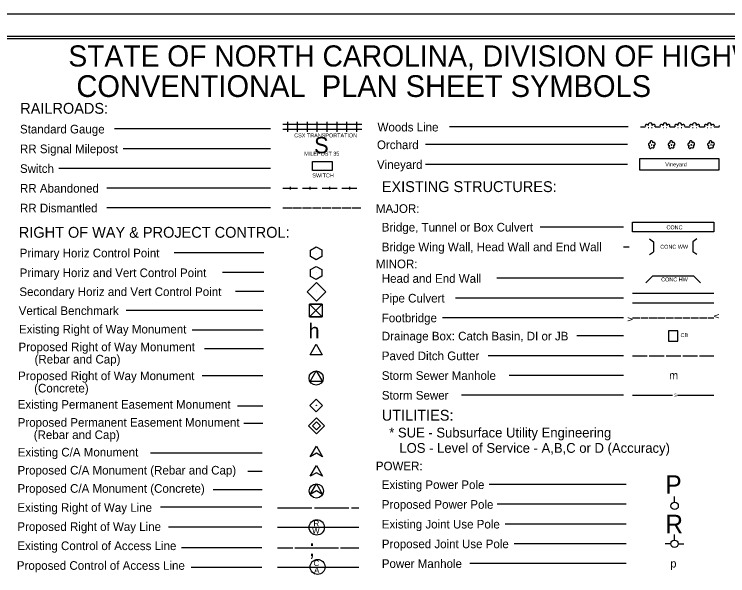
# Model space of a CAD drawing. Extents: x -167 to 1517, y -26 to 1074.
# Drawn here: x 396 to 1119, y 505 to 1074 of the extents above; entities that cross this region are included whole.
import ezdxf

# ---------------------------------------------------------------- set-up
doc = ezdxf.new("R2010")
doc.units = 0
for name, color, linetype in [('Default', 7, 'Continuous'), ('Sheet Cutting Line CELL', 7, 'Continuous'), ('Sheet Plot Border Inside CELL', 7, 'Continuous'), ('Sheet Plot Border Outside CELL', 7, 'Continuous'), ('Sheet Symbology CELL', 7, 'Continuous')]:
    doc.layers.add(name, color=color, linetype=linetype)

msp = doc.modelspace()

# ---------------------------------------------------------------- linework, layer by layer
at = {"layer": 'Default'}
for p, q in [((701.87, 831.68), (701.87, 831.68)), ((701.86, 811.71), (701.86, 811.71)), ((702, 792.64), (702, 792.64)), ((701.49, 773.64), (701.49, 773.64)), ((701.96, 677.42), (701.96, 677.42)), ((702.14, 656.81), (702.14, 656.81))]:
    msp.add_line(p, q, dxfattribs=at)
for points in [[(701.87, 825.03), (696.07, 828.32), (696.07, 834.97), (701.87, 838.33), (707.66, 835.04), (707.66, 828.32), (701.87, 825.03)], [(707.97, 780.11), (695, 767.14), (701.48, 773.63), (707.97, 767.14), (695, 780.11)], [(701.48, 773.63), (707.97, 780.11), (695, 780.11), (701.48, 773.63)], [(701.48, 773.63), (695, 767.14), (707.97, 767.14), (701.48, 773.63)]]:
    msp.add_lwpolyline(points, dxfattribs=at)
for points in [[(696.03, 815.09), (701.89, 818.36), (707.76, 815.13), (707.67, 808.41), (701.8, 805.01), (696.03, 808.28)], [(692.59, 792.67), (702.04, 802.13), (711.52, 792.65), (702.06, 783.2)], [(695, 780.11), (707.97, 780.11), (707.97, 767.14), (695, 767.14)], [(695.46, 677.42), (701.96, 683.91), (708.45, 677.42), (701.96, 670.92)], [(702.14, 664.86), (710.19, 656.81), (702.14, 648.76), (694.08, 656.81)], [(702.14, 660.84), (706.16, 656.81), (702.14, 652.79), (698.11, 656.81)]]:
    msp.add_lwpolyline(points, close=True, dxfattribs=at)
msp.add_circle((701.96, 677.42), 0.126, dxfattribs=at)
at = {"layer": 'Sheet Cutting Line CELL'}
msp.add_line((1517, 1073.98), (-167, 1073.98), dxfattribs=at)
at = {"layer": 'Sheet Plot Border Inside CELL'}
msp.add_lwpolyline([(-154, -3.57), (1512.5, -3.57), (1512.5, 1051.53), (-154, 1051.53)], close=True, dxfattribs=at)
at = {"layer": 'Sheet Plot Border Outside CELL'}
msp.add_lwpolyline([(-167, -26.02), (1517, -26.02), (1517, 1073.98), (-167, 1073.98)], close=True, dxfattribs=at)
at = {"layer": 'Sheet Symbology CELL'}
for p, q in [((668.02, 962.44), (678.02, 962.44)), ((673.02, 954.94), (673.02, 964.94)), ((678.02, 962.44), (688.02, 962.44)), ((683.02, 954.94), (683.02, 964.94)), ((688.02, 962.44), (698.02, 962.44)), ((693.02, 954.94), (693.02, 964.94)), ((698.02, 962.44), (708.02, 962.44)), ((703.02, 954.94), (703.02, 964.94)), ((708.02, 962.44), (718.02, 962.44)), ((713.02, 954.94), (713.02, 964.94)), ((718.02, 962.44), (728.02, 962.44)), ((723.02, 954.94), (723.02, 964.94)), ((728.02, 962.44), (738.02, 962.44)), ((733.02, 954.94), (733.02, 964.94)), ((738.02, 962.44), (748.02, 962.44)), ((743.02, 954.94), (743.02, 964.94)), ((655.63, 957.67), (497.22, 957.67)), ((668.02, 957.44), (678.02, 957.44)), ((678.02, 957.44), (688.02, 957.44)), ((688.02, 957.44), (698.02, 957.44)), ((698.02, 957.44), (708.02, 957.44)), ((708.02, 957.44), (718.02, 957.44)), ((718.02, 957.44), (728.02, 957.44)), ((728.02, 957.44), (738.02, 957.44)), ((738.02, 957.44), (748.02, 957.44)), ((1018.26, 959.72), (837.14, 959.72)), ((1030.65, 959.72), (1035.65, 959.72)), ((1038.6, 959.22), (1039.1, 959.22)), ((1042.1, 959.22), (1042.6, 959.22)), ((1045.65, 959.72), (1050.65, 959.72)), ((1053.6, 959.22), (1054.1, 959.22)), ((1057.1, 959.22), (1057.6, 959.22)), ((1060.65, 959.72), (1065.65, 959.72)), ((1068.6, 959.22), (1069.1, 959.22)), ((1072.1, 959.22), (1072.6, 959.22)), ((1075.65, 959.72), (1080.65, 959.72)), ((1083.6, 959.22), (1084.1, 959.22)), ((1087.1, 959.22), (1087.6, 959.22)), ((1090.65, 959.72), (1095.65, 959.72)), ((1098.6, 959.22), (1099.1, 959.22)), ((1102.1, 959.22), (1102.6, 959.22)), ((1105.65, 959.72), (1110.65, 959.72)), ((1017.7, 941.79), (812.76, 941.79)), ((655.63, 937.67), (506.08, 937.67)), ((1017.7, 921.79), (812.76, 921.79)), ((655.63, 917.67), (440.72, 917.67)), ((655.63, 897.67), (489.47, 897.67)), ((668.02, 897.67), (683.02, 897.67)), ((675.52, 898.92), (675.52, 896.42)), ((688.02, 897.67), (703.02, 897.67)), ((695.52, 898.92), (695.52, 896.42)), ((708.02, 897.67), (723.02, 897.67)), ((715.52, 898.92), (715.52, 896.42)), ((728.02, 897.67), (743.02, 897.67)), ((735.52, 898.92), (735.52, 896.42)), ((655.63, 877.67), (489.47, 877.67)), ((655.63, 877.67), (489.47, 877.67)), ((668.02, 877.67), (677.02, 877.67)), ((678.02, 877.67), (687.02, 877.67)), ((688.02, 877.67), (697.02, 877.67)), ((698.02, 877.67), (707.02, 877.67)), ((708.02, 877.67), (717.02, 877.67)), ((718.02, 877.67), (727.02, 877.67)), ((728.02, 877.67), (737.02, 877.67)), ((738.02, 877.67), (747.02, 877.67)), ((1013.38, 858.28), (928.96, 858.28)), ((1039.83, 846.15), (1043.93, 843.28)), ((1043.93, 843.28), (1043.93, 833.28)), ((1088.03, 846.15), (1083.93, 843.28)), ((1083.93, 843.28), (1083.93, 833.28)), ((1013.38, 838.28), (1019.37, 838.28)), ((1039.83, 830.42), (1043.93, 833.28)), ((1088.03, 830.42), (1083.93, 833.28)), ((648.94, 832.05), (557.9, 832.05)), ((648.94, 812.05), (607.02, 812.05)), ((1013.38, 806.29), (885.08, 806.29)), ((1036.23, 801.71), (1043.31, 808.79)), ((1043.31, 808.79), (1084.56, 808.79)), ((1084.56, 808.79), (1091.63, 801.71)), ((648.62, 792.85), (620.07, 792.85)), ((1022.68, 791.29), (1105.18, 791.29)), ((1013.38, 786.29), (843.19, 786.29)), ((1022.68, 781.29), (1105.18, 781.29)), ((647.93, 773.63), (509.09, 773.63)), ((1013.38, 766.29), (829.91, 766.29)), ((1022.68, 766.29), (1030.18, 766.29)), ((1031.18, 766.29), (1038.68, 766.29)), ((1039.68, 766.29), (1047.18, 766.29)), ((1048.18, 766.29), (1055.68, 766.29)), ((1056.68, 766.29), (1064.18, 766.29)), ((1065.18, 766.29), (1072.68, 766.29)), ((1073.68, 766.29), (1081.18, 766.29)), ((1082.18, 766.29), (1089.68, 766.29)), ((1090.68, 766.29), (1098.18, 766.29)), ((1099.18, 766.29), (1105.18, 766.29)), ((648.25, 753.64), (576.2, 753.64)), ((1013.38, 747.85), (966.18, 747.85)), ((648.35, 734.86), (588.61, 734.86)), ((701.86, 732.24), (701.86, 732.24)), ((1013.38, 727.85), (876.43, 727.85)), ((1022.68, 727.85), (1037.68, 727.85)), ((1039.68, 727.85), (1054.68, 727.85)), ((1056.68, 727.85), (1071.68, 727.85)), ((1073.68, 727.85), (1088.68, 727.85)), ((1090.68, 727.85), (1105.18, 727.85)), ((647.84, 707.46), (586.36, 707.46)), ((701.88, 705.18), (701.88, 705.18)), ((1013.38, 707.85), (897.71, 707.85)), ((1013.38, 687.85), (849.18, 687.85)), ((1022.68, 687.85), (1063.21, 687.85)), ((1068.21, 687.85), (1105.18, 687.85)), ((647.92, 676.76), (622.13, 676.76)), ((647.92, 659.14), (628.65, 659.14)), ((695.87, 625.24), (702.12, 636.04)), ((702.12, 636.04), (708.37, 625.24)), ((646.93, 628.92), (533.69, 628.92)), ((702.12, 628.84), (695.87, 625.24)), ((708.37, 625.24), (702.12, 628.84)), ((695.84, 605.62), (702.09, 616.42)), ((702.09, 616.42), (708.34, 605.62)), ((647.03, 610.39), (632.46, 610.39)), ((702.09, 609.22), (695.84, 605.62)), ((708.34, 605.62), (702.09, 609.22)), ((695.84, 587.12), (702.09, 597.92)), ((702.09, 597.92), (708.34, 587.12)), ((1016.17, 597.17), (877.47, 597.17)), ((647.03, 591.88), (597.36, 591.88)), ((702.09, 590.72), (695.84, 587.12)), ((708.34, 587.12), (702.09, 590.72)), ((1065.39, 579.28), (1065.39, 584.91)), ((646.59, 574.1), (544.07, 574.1)), ((662.62, 573.53), (697.62, 573.53)), ((700.12, 573.53), (735.12, 573.53)), ((737.62, 573.53), (745.12, 573.53)), ((1016.17, 577.17), (885.26, 577.17)), ((1016.17, 557.17), (893.66, 557.17)), ((646.59, 554.1), (552.06, 554.1)), ((662.62, 553.98), (745.12, 553.98)), ((1065.18, 540.93), (1065.18, 546.56)), ((1016.17, 537.17), (902.66, 537.17)), ((1061.43, 537.18), (1055.81, 537.18)), ((1068.93, 537.18), (1074.56, 537.18)), ((646.59, 532.98), (565.27, 532.98)), ((662.62, 532.98), (678.08, 532.98)), ((680.08, 532.98), (724.49, 532.98)), ((726.49, 532.98), (745.12, 532.98)), ((1016.17, 517.17), (857.67, 517.17)), ((646.59, 513.16), (574.94, 513.16)), ((662.62, 513.54), (745.12, 513.54))]:
    msp.add_line(p, q, dxfattribs=at)
for points in [[(1500, 1048.98), (0, 1048.98), (0, 0), (1500, 0)], [(698.02, 924.64), (718.02, 924.64), (718.02, 915.54), (698.02, 915.54)], [(1059.12, 742.54), (1068.73, 742.54), (1068.73, 753.18), (1059.12, 753.18)], [(695.61, 728.64), (701.86, 739.44), (708.11, 728.64)], [(695.63, 701.58), (701.88, 712.38), (708.13, 701.58)]]:
    msp.add_lwpolyline(points, close=True, dxfattribs=at)
for points in [[(1043.14, 943.54), (1043.29, 943.84), (1043.34, 944.14), (1043.29, 944.44), (1043.24, 944.74), (1043.09, 944.99), (1042.94, 945.24), (1042.69, 945.44), (1042.44, 945.59), (1042.09, 945.69), (1041.84, 945.69), (1041.54, 945.64), (1041.24, 945.54), (1040.99, 945.39), (1040.74, 945.19), (1040.59, 944.89), (1040.49, 944.64), (1040.44, 944.34), (1040.44, 944.04), (1040.49, 943.74), (1040.64, 943.49), (1040.84, 943.19), (1040.59, 943.34), (1040.29, 943.39), (1039.99, 943.39), (1039.74, 943.29), (1039.49, 943.19), (1039.24, 942.99), (1039.04, 942.79), (1038.89, 942.54), (1038.84, 942.29), (1038.79, 941.94), (1038.84, 941.69), (1038.94, 941.44), (1039.14, 941.19), (1039.29, 940.99), (1039.54, 940.84), (1039.84, 940.69), (1040.09, 940.64), (1040.39, 940.64), (1040.14, 940.54), (1039.89, 940.34), (1039.74, 940.14), (1039.64, 939.84), (1039.54, 939.54), (1039.54, 939.29), (1039.59, 938.99), (1039.74, 938.74), (1039.89, 938.49), (1040.09, 938.29), (1040.34, 938.14), (1040.59, 938.04), (1040.89, 938.04), (1041.19, 938.04), (1041.44, 938.09), (1041.69, 938.29), (1041.94, 938.44), (1042.19, 938.89)], [(1042.29, 941.79), (1042.14, 941.79), (1042.04, 941.74), (1041.94, 941.69), (1041.94, 941.54), (1041.94, 941.44), (1042.04, 941.34), (1042.19, 941.34), (1042.29, 941.34), (1042.39, 941.44), (1042.44, 941.59), (1042.39, 941.69), (1042.29, 941.79)], [(1042.19, 938.89), (1042.79, 938.54), (1043.09, 938.44), (1043.39, 938.39), (1043.69, 938.44), (1043.94, 938.54), (1044.19, 938.69), (1044.44, 938.89), (1044.59, 939.14), (1044.69, 939.39), (1044.79, 939.69), (1044.74, 939.99), (1044.69, 940.29), (1044.49, 940.59), (1044.34, 940.79), (1044.09, 940.94), (1043.79, 941.09), (1044.09, 941.04), (1044.44, 941.04), (1044.69, 941.14), (1044.99, 941.29), (1045.24, 941.44), (1045.44, 941.69), (1045.59, 941.99), (1045.64, 942.29), (1045.69, 942.59), (1045.64, 942.89), (1045.54, 943.19), (1045.34, 943.44), (1045.09, 943.69), (1044.84, 943.84), (1044.54, 943.94), (1044.24, 943.99), (1043.94, 943.99), (1043.64, 943.89), (1043.39, 943.74), (1043.14, 943.54)], [(1063.14, 943.54), (1063.29, 943.84), (1063.34, 944.14), (1063.29, 944.44), (1063.24, 944.74), (1063.09, 944.99), (1062.94, 945.24), (1062.69, 945.44), (1062.44, 945.59), (1062.09, 945.69), (1061.84, 945.69), (1061.54, 945.64), (1061.24, 945.54), (1060.99, 945.39), (1060.74, 945.19), (1060.59, 944.89), (1060.49, 944.64), (1060.44, 944.34), (1060.44, 944.04), (1060.49, 943.74), (1060.64, 943.49), (1060.84, 943.19), (1060.59, 943.34), (1060.29, 943.39), (1059.99, 943.39), (1059.74, 943.29), (1059.49, 943.19), (1059.24, 942.99), (1059.04, 942.79), (1058.89, 942.54), (1058.84, 942.29), (1058.79, 941.94), (1058.84, 941.69), (1058.94, 941.44), (1059.14, 941.19), (1059.29, 940.99), (1059.54, 940.84), (1059.84, 940.69), (1060.09, 940.64), (1060.39, 940.64), (1060.14, 940.54), (1059.89, 940.34), (1059.74, 940.14), (1059.64, 939.84), (1059.54, 939.54), (1059.54, 939.29), (1059.59, 938.99), (1059.74, 938.74), (1059.89, 938.49), (1060.09, 938.29), (1060.34, 938.14), (1060.59, 938.04), (1060.89, 938.04), (1061.19, 938.04), (1061.44, 938.09), (1061.69, 938.29), (1061.94, 938.44), (1062.19, 938.89)], [(1062.29, 941.79), (1062.14, 941.79), (1062.04, 941.74), (1061.94, 941.69), (1061.94, 941.54), (1061.94, 941.44), (1062.04, 941.34), (1062.19, 941.34), (1062.29, 941.34), (1062.39, 941.44), (1062.44, 941.59), (1062.39, 941.69), (1062.29, 941.79)], [(1062.19, 938.89), (1062.79, 938.54), (1063.09, 938.44), (1063.39, 938.39), (1063.69, 938.44), (1063.94, 938.54), (1064.19, 938.69), (1064.44, 938.89), (1064.59, 939.14), (1064.69, 939.39), (1064.79, 939.69), (1064.74, 939.99), (1064.69, 940.29), (1064.49, 940.59), (1064.34, 940.79), (1064.09, 940.94), (1063.79, 941.09), (1064.09, 941.04), (1064.44, 941.04), (1064.69, 941.14), (1064.99, 941.29), (1065.24, 941.44), (1065.44, 941.69), (1065.59, 941.99), (1065.64, 942.29), (1065.69, 942.59), (1065.64, 942.89), (1065.54, 943.19), (1065.34, 943.44), (1065.09, 943.69), (1064.84, 943.84), (1064.54, 943.94), (1064.24, 943.99), (1063.94, 943.99), (1063.64, 943.89), (1063.39, 943.74), (1063.14, 943.54)], [(1083.14, 943.54), (1083.29, 943.84), (1083.34, 944.14), (1083.29, 944.44), (1083.24, 944.74), (1083.09, 944.99), (1082.94, 945.24), (1082.69, 945.44), (1082.44, 945.59), (1082.09, 945.69), (1081.84, 945.69), (1081.54, 945.64), (1081.24, 945.54), (1080.99, 945.39), (1080.74, 945.19), (1080.59, 944.89), (1080.49, 944.64), (1080.44, 944.34), (1080.44, 944.04), (1080.49, 943.74), (1080.64, 943.49), (1080.84, 943.19), (1080.59, 943.34), (1080.29, 943.39), (1079.99, 943.39), (1079.74, 943.29), (1079.49, 943.19), (1079.24, 942.99), (1079.04, 942.79), (1078.89, 942.54), (1078.84, 942.29), (1078.79, 941.94), (1078.84, 941.69), (1078.94, 941.44), (1079.14, 941.19), (1079.29, 940.99), (1079.54, 940.84), (1079.84, 940.69), (1080.09, 940.64), (1080.39, 940.64), (1080.14, 940.54), (1079.89, 940.34), (1079.74, 940.14), (1079.64, 939.84), (1079.54, 939.54), (1079.54, 939.29), (1079.59, 938.99), (1079.74, 938.74), (1079.89, 938.49), (1080.09, 938.29), (1080.34, 938.14), (1080.59, 938.04), (1080.89, 938.04), (1081.19, 938.04), (1081.44, 938.09), (1081.69, 938.29), (1081.94, 938.44), (1082.19, 938.89)], [(1082.29, 941.79), (1082.14, 941.79), (1082.04, 941.74), (1081.94, 941.69), (1081.94, 941.54), (1081.94, 941.44), (1082.04, 941.34), (1082.19, 941.34), (1082.29, 941.34), (1082.39, 941.44), (1082.44, 941.59), (1082.39, 941.69), (1082.29, 941.79)], [(1082.19, 938.89), (1082.79, 938.54), (1083.09, 938.44), (1083.39, 938.39), (1083.69, 938.44), (1083.94, 938.54), (1084.19, 938.69), (1084.44, 938.89), (1084.59, 939.14), (1084.69, 939.39), (1084.79, 939.69), (1084.74, 939.99), (1084.69, 940.29), (1084.49, 940.59), (1084.34, 940.79), (1084.09, 940.94), (1083.79, 941.09), (1084.09, 941.04), (1084.44, 941.04), (1084.69, 941.14), (1084.99, 941.29), (1085.24, 941.44), (1085.44, 941.69), (1085.59, 941.99), (1085.64, 942.29), (1085.69, 942.59), (1085.64, 942.89), (1085.54, 943.19), (1085.34, 943.44), (1085.09, 943.69), (1084.84, 943.84), (1084.54, 943.94), (1084.24, 943.99), (1083.94, 943.99), (1083.64, 943.89), (1083.39, 943.74), (1083.14, 943.54)], [(1103.14, 943.54), (1103.29, 943.84), (1103.34, 944.14), (1103.29, 944.44), (1103.24, 944.74), (1103.09, 944.99), (1102.94, 945.24), (1102.69, 945.44), (1102.44, 945.59), (1102.09, 945.69), (1101.84, 945.69), (1101.54, 945.64), (1101.24, 945.54), (1100.99, 945.39), (1100.74, 945.19), (1100.59, 944.89), (1100.49, 944.64), (1100.44, 944.34), (1100.44, 944.04), (1100.49, 943.74), (1100.64, 943.49), (1100.84, 943.19), (1100.59, 943.34), (1100.29, 943.39), (1099.99, 943.39), (1099.74, 943.29), (1099.49, 943.19), (1099.24, 942.99), (1099.04, 942.79), (1098.89, 942.54), (1098.84, 942.29), (1098.79, 941.94), (1098.84, 941.69), (1098.94, 941.44), (1099.14, 941.19), (1099.29, 940.99), (1099.54, 940.84), (1099.84, 940.69), (1100.09, 940.64), (1100.39, 940.64), (1100.14, 940.54), (1099.89, 940.34), (1099.74, 940.14), (1099.64, 939.84), (1099.54, 939.54), (1099.54, 939.29), (1099.59, 938.99), (1099.74, 938.74), (1099.89, 938.49), (1100.09, 938.29), (1100.34, 938.14), (1100.59, 938.04), (1100.89, 938.04), (1101.19, 938.04), (1101.44, 938.09), (1101.69, 938.29), (1101.94, 938.44), (1102.19, 938.89)], [(1102.29, 941.79), (1102.14, 941.79), (1102.04, 941.74), (1101.94, 941.69), (1101.94, 941.54), (1101.94, 941.44), (1102.04, 941.34), (1102.19, 941.34), (1102.29, 941.34), (1102.39, 941.44), (1102.44, 941.59), (1102.39, 941.69), (1102.29, 941.79)], [(1102.19, 938.89), (1102.79, 938.54), (1103.09, 938.44), (1103.39, 938.39), (1103.69, 938.44), (1103.94, 938.54), (1104.19, 938.69), (1104.44, 938.89), (1104.59, 939.14), (1104.69, 939.39), (1104.79, 939.69), (1104.74, 939.99), (1104.69, 940.29), (1104.49, 940.59), (1104.34, 940.79), (1104.09, 940.94), (1103.79, 941.09), (1104.09, 941.04), (1104.44, 941.04), (1104.69, 941.14), (1104.99, 941.29), (1105.24, 941.44), (1105.44, 941.69), (1105.59, 941.99), (1105.64, 942.29), (1105.69, 942.59), (1105.64, 942.89), (1105.54, 943.19), (1105.34, 943.44), (1105.09, 943.69), (1104.84, 943.84), (1104.54, 943.94), (1104.24, 943.99), (1103.94, 943.99), (1103.64, 943.89), (1103.39, 943.74), (1103.14, 943.54)], [(1030.09, 927.79), (1110.09, 927.79), (1110.09, 915.79), (1030.09, 915.79), (1030.09, 927.79)], [(1022.68, 863.28), (1105.18, 863.28), (1105.18, 853.28), (1022.68, 853.28), (1022.68, 863.28)]]:
    msp.add_lwpolyline(points, dxfattribs=at)
for centre, radius in [((701.88, 705.18), 7.2), ((702.09, 590.72), 7.2), ((1065.39, 575.53), 3.75), ((702.47, 553.77), 7.75), ((1065.18, 537.17), 3.75), ((703.27, 513.65), 7.58)]:
    msp.add_circle(centre, radius, dxfattribs=at)
for centre, radius, start, end in [((1040.6, 961.73), 2.06, 345.96376, 194.03624), ((1055.6, 961.73), 2.06, 345.96376, 194.03624), ((1070.6, 961.73), 2.06, 345.96376, 194.03624), ((1085.6, 961.73), 2.06, 345.96376, 194.03624), ((1100.6, 961.73), 2.06, 345.96376, 194.03624), ((1037.1, 960.73), 1.58, 18.43495, 219.23152), ((1044.1, 960.73), 1.58, 320.76848, 161.56505), ((1052.1, 960.73), 1.58, 18.43495, 219.23152), ((1059.1, 960.73), 1.58, 320.76848, 161.56505), ((1067.1, 960.73), 1.58, 18.43495, 219.23152), ((1074.1, 960.73), 1.58, 320.76848, 161.56505), ((1082.1, 960.73), 1.58, 18.43495, 219.23152), ((1089.1, 960.73), 1.58, 320.76848, 161.56505), ((1097.1, 960.73), 1.58, 18.43495, 219.23152), ((1104.1, 960.73), 1.58, 320.76848, 161.56505), ((1112.1, 960.73), 1.58, 156.25102, 203.74899)]:
    msp.add_arc(centre, radius, start, end, dxfattribs=at)

# ---------------------------------------------------------------- texts
for s, height, p in [('STATE OF NORTH CAROLINA, DIVISION OF HIGHWAYS', 21.419, (450.56, 1021.02)), ('CONVENTIONAL  PLAN SHEET SYMBOLS', 22.0323, (458.69, 990.14)), ('RAILROADS:', 11, (401.74, 973.12)), ('Standard Gauge', 8.75, (401.47, 953.15)), ('Woods Line', 8.75, (764.1, 955.19)), ('S', 16.5, (699.78, 933.05)), ('RR Signal Milepost', 8.75, (401.47, 933.15)), ('Orchard', 8.75, (763.53, 937.26)), ('Vineyard', 8.75, (763.53, 917.26)), ('Switch', 8.75, (401.47, 913.15)), ('EXISTING STRUCTURES:', 11, (768.42, 893.73)), ('RR Abandoned', 8.75, (401.47, 893.15)), ('RR Dismantled', 8.75, (401.47, 873.15)), ('MAJOR:', 8.75, (762.39, 872.62)), ('Bridge, Tunnel or Box Culvert', 8.75, (768.42, 853.73)), ('RIGHT OF WAY & PROJECT CONTROL:', 11, (400.33, 847.4)), ('CONC', 4, (1057.12, 855.92)), ('Bridge Wing Wall, Head Wall and End Wall', 8.75, (768.42, 833.73)), ('Primary Horiz Control Point', 8.75, (401.19, 827.5)), ('MINOR:', 8.75, (762.39, 816.5)), ('Primary Horiz and Vert Control Point', 8.75, (401.19, 807.5)), ('Head and End Wall', 8.75, (768.42, 801.74)), ('Secondary Horiz and Vert Control Point', 8.75, (400.87, 788.3)), ('Pipe Culvert', 8.75, (768.42, 781.75)), ('Vertical Benchmark', 8.75, (400.18, 769.08)), ('Footbridge', 8.75, (768.43, 761.75)), ('h', 15, (694.1, 745.46)), ('Existing Right of Way Monument', 8.75, (400.5, 750.36)), ('Drainage Box: Catch Basin, DI or JB', 8.75, (768.43, 743.32)), ('Proposed Right of Way Monument', 8.75, (399.98, 732.39)), ('Paved Ditch Gutter', 8.75, (768.43, 723.3)), ('     (Rebar and Cap)', 8.75, (399.98, 719.89)), ('Proposed Right of Way Monument', 8.75, (399.6, 703.04)), ('Storm Sewer Manhole', 8.75, (768.43, 703.3)), ('m', 8.25, (1059.81, 703.73)), ('     (Concrete)', 8.75, (399.6, 690.54)), ('Storm Sewer', 8.75, (768.43, 683.3)), ('S', 3, (1064.81, 686.35)), ('Existing Permanent Easement Monument', 8.75, (399.12, 674.05)), ('UTILITIES:', 11, (768.42, 661.94)), ('Proposed Permanent Easement Monument', 8.75, (399.16, 655.81)), ('     (Rebar and Cap)', 8.75, (399.16, 643.31)), ('Existing C/A Monument', 8.75, (399.18, 625.64)), ('Proposed C/A Monument (Rebar and Cap)', 8.75, (398.97, 607.34)), ('POWER:', 8.75, (762.39, 611.63)), ('Existing Power Pole', 8.75, (768.43, 592.63)), ('P', 18.75, (1055.81, 587.8)), ('Proposed C/A Monument (Concrete)', 8.75, (398.97, 588.83)), ('Proposed Power Pole', 8.75, (768.43, 572.63)), ('Existing Right of Way Line', 8.75, (398.84, 569.55)), ('R', 18.75, (1055.81, 547.8)), ('Proposed Right of Way Line', 8.75, (398.84, 550.18)), ('R', 6.08, (699.14, 554.69)), ('Existing Joint Use Pole', 8.75, (768.43, 552.65)), ('W', 6.08, (697.75, 547.53)), ('Existing Control of Access Line', 8.75, (398.84, 530.72)), (';', 16.5, (694.41, 524.79)), ('Proposed Joint Use Pole', 8.75, (768.44, 532.63)), ('Power Manhole', 8.75, (768.44, 512.63)), ('Proposed Control of Access Line', 8.75, (398.29, 510.73)), ('C', 5.94, (699.24, 514.54)), ('p', 8.25, (1061.06, 513.05)), ('A', 5.94, (699.83, 507.41))]:
    msp.add_text(s, height=height, dxfattribs=at).set_placement(p)
for s, height, rotation, p in [('CSX TRANSPORTATION', 4, 360, (679.58, 949.2)), ('MILEPOST 35', 4, 360, (689.77, 930.62)), ('Vineyard', 4, 0.00002, (1055.91, 919.79)), ('SWITCH', 4, 360, (697.97, 908.62)), ('CONC WW', 4, 0.00002, (1050.81, 836.28)), ('CONC HW', 4, 360, (1051.73, 803.13)), ('v', 6.6, 270.24085, (1105.17, 770.03)), ('v', 6.6, 89.75915, (1022.67, 762.55)), ('CB', 4, 360, (1071.37, 746.68)), ('* SUE - Subsurface Utility Engineering', 9.9, 360, (775.95, 644.92)), ('LOS - Level of Service - A,B,C or D (Accuracy) ', 9.9, 360, (786.22, 629.35))]:
    msp.add_text(s, height=height, rotation=rotation, dxfattribs=at).set_placement(p)

doc.saveas('drawing.dxf')
